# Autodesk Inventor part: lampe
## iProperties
Created: 2011-01
Part Number: lampe
Document SubType Name: Modeling
Designer: eric
Density: 1 g/cm^3
Mass: 7.25417 g
Surface Area: 74.121 cm^2
Volume: 7.25417 cm^3
Author: eric
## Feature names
1. Base1
